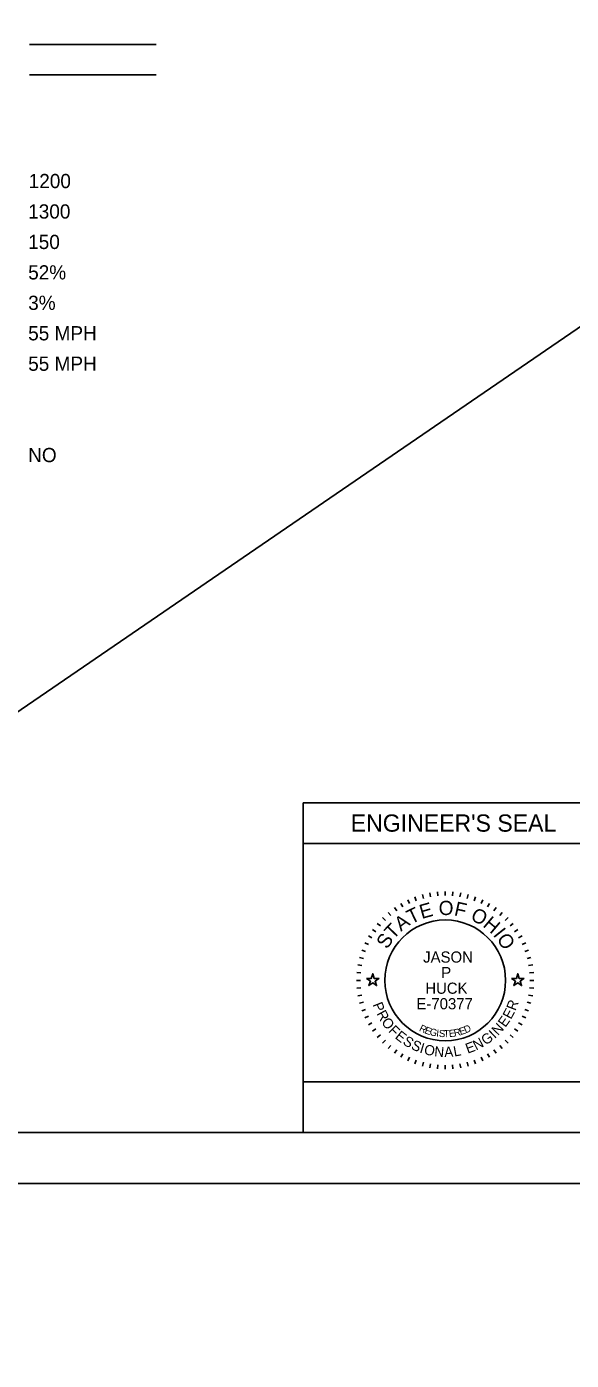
# Model space of a CAD drawing. Extents: x -1.8 to 75.7, y -2 to 25.
# Drawn here: x 7.72 to 13.09, y -1.74 to 11.4 of the extents above; entities that cross this region are included whole.
import ezdxf

# ---------------------------------------------------------------- set-up
doc = ezdxf.new("R2010")
doc.units = 0
for name, color, linetype in [('Default', 7, 'Continuous'), ('SH_Border', 7, 'Continuous'), ('SH_Cut_Line', 7, 'Continuous'), ('SH_Data', 7, 'Continuous'), ('SH_Text', 7, 'Continuous'), ('TX_P_1', 7, 'Continuous')]:
    doc.layers.add(name, color=color, linetype=linetype)

msp = doc.modelspace()

# ---------------------------------------------------------------- linework, layer by layer
at = {"layer": 'Default'}
for points in [[(11.074, 2.02), (11.121, 2.02), (11.135, 2.065), (11.149, 2.02), (11.196, 2.02), (11.158, 1.992), (11.173, 1.948), (11.135, 1.975), (11.097, 1.948), (11.112, 1.992)], [(12.504, 2.02), (12.551, 2.02), (12.565, 2.065), (12.579, 2.02), (12.626, 2.02), (12.588, 1.992), (12.603, 1.948), (12.565, 1.975), (12.527, 1.948), (12.542, 1.992)]]:
    msp.add_lwpolyline(points, close=True, dxfattribs=at)
at = {"layer": 'SH_Border'}
msp.add_lwpolyline([(1.5, 21.5), (33.5, 21.5), (33.5, 0.5), (1.5, 0.5)], close=True, dxfattribs=at)
at = {"layer": 'SH_Cut_Line'}
msp.add_lwpolyline([(0, 0), (34, 0), (34, 22), (0, 22)], close=True, dxfattribs=at)
at = {"layer": 'SH_Data'}
for p, q in [((9, 11.222), (7.75, 11.222)), ((9, 10.922), (7.75, 10.922)), ((13.25, 3.75), (10.45, 3.75)), ((10.45, 3.75), (10.45, 0.5)), ((13.25, 3.35), (10.45, 3.35)), ((11.48, 2.793), (11.497, 2.757)), ((11.551, 2.822), (11.564, 2.785)), ((11.624, 2.845), (11.634, 2.807)), ((11.698, 2.862), (11.705, 2.822)), ((11.774, 2.872), (11.777, 2.832)), ((11.85, 2.875), (11.85, 2.835)), ((11.926, 2.872), (11.923, 2.832)), ((12.002, 2.862), (11.995, 2.822)), ((12.076, 2.845), (12.066, 2.807)), ((12.149, 2.822), (12.136, 2.785)), ((12.22, 2.793), (12.203, 2.757)), ((11.288, 2.67), (11.313, 2.64)), ((11.348, 2.717), (11.371, 2.684)), ((11.413, 2.758), (11.433, 2.723)), ((12.287, 2.758), (12.267, 2.723)), ((12.352, 2.717), (12.329, 2.684)), ((12.412, 2.67), (12.387, 2.64)), ((11.133, 2.502), (11.166, 2.479)), ((11.18, 2.562), (11.21, 2.537)), ((11.231, 2.619), (11.26, 2.59)), ((12.469, 2.619), (12.44, 2.59)), ((12.52, 2.562), (12.49, 2.537)), ((12.567, 2.502), (12.534, 2.479)), ((11.057, 2.37), (11.093, 2.353)), ((11.092, 2.438), (11.127, 2.418)), ((12.608, 2.438), (12.573, 2.418)), ((12.643, 2.37), (12.607, 2.353)), ((11.028, 2.299), (11.065, 2.286)), ((12.672, 2.299), (12.635, 2.286)), ((10.988, 2.152), (11.028, 2.145)), ((11.005, 2.226), (11.043, 2.216)), ((12.695, 2.226), (12.657, 2.216)), ((12.712, 2.152), (12.672, 2.145)), ((10.975, 2), (11.015, 2)), ((10.978, 2.076), (11.018, 2.073)), ((12.722, 2.076), (12.682, 2.073)), ((12.725, 2), (12.685, 2)), ((10.978, 1.924), (11.018, 1.927)), ((10.988, 1.848), (11.028, 1.855)), ((12.712, 1.848), (12.672, 1.855)), ((12.722, 1.924), (12.682, 1.927)), ((11.005, 1.774), (11.043, 1.784)), ((11.028, 1.701), (11.065, 1.714)), ((12.672, 1.701), (12.635, 1.714)), ((12.695, 1.774), (12.657, 1.784)), ((11.057, 1.63), (11.093, 1.647)), ((11.092, 1.563), (11.127, 1.583)), ((12.608, 1.563), (12.573, 1.583)), ((12.643, 1.63), (12.607, 1.647)), ((11.133, 1.498), (11.166, 1.521)), ((11.18, 1.438), (11.21, 1.463)), ((12.52, 1.438), (12.49, 1.463)), ((12.567, 1.498), (12.534, 1.521)), ((11.231, 1.381), (11.26, 1.41)), ((11.288, 1.33), (11.313, 1.36)), ((11.348, 1.283), (11.371, 1.316)), ((12.352, 1.283), (12.329, 1.316)), ((12.412, 1.33), (12.387, 1.36)), ((12.469, 1.381), (12.44, 1.41)), ((11.413, 1.242), (11.433, 1.277)), ((11.48, 1.207), (11.497, 1.243)), ((11.551, 1.178), (11.564, 1.215)), ((11.624, 1.155), (11.634, 1.193)), ((12.076, 1.155), (12.066, 1.193)), ((12.149, 1.178), (12.136, 1.215)), ((12.22, 1.207), (12.203, 1.243)), ((12.287, 1.242), (12.267, 1.277)), ((11.698, 1.138), (11.705, 1.178)), ((11.774, 1.128), (11.777, 1.168)), ((11.85, 1.125), (11.85, 1.165)), ((11.926, 1.128), (11.923, 1.168)), ((12.002, 1.138), (11.995, 1.178)), ((13.25, 0.5), (10.45, 0.5))]:
    msp.add_line(p, q, dxfattribs=at)
msp.add_lwpolyline([(13.25, 0.5), (13.25, 1), (10.45, 1), (10.45, 0.5)], close=True, dxfattribs=at)
msp.add_circle((11.85, 2), 0.595, dxfattribs=at)
at = {"layer": 'TX_P_1'}
msp.add_line((37.367, 24.993), (-1.706, -1.744), dxfattribs=at)

# ---------------------------------------------------------------- texts
at = {"layer": 'SH_Data'}
for s, height, p in [("ENGINEER'S SEAL", 0.17, (10.918, 3.465)), ('JASON', 0.11, (11.632, 2.175)), ('P', 0.11, (11.81, 2.022)), ('HUCK', 0.11, (11.653, 1.868)), ('E-70377', 0.11, (11.566, 1.715))]:
    msp.add_text(s, height=height, dxfattribs=at).set_placement(p)
for s, height, rotation, p in [('E', 0.14, 15.7571, (11.618, 2.604)), ('O', 0.14, 359.7812, (11.785, 2.644)), ('F', 0.14, 347.4362, (11.931, 2.642)), ('A', 0.14, 36.4747, (11.413, 2.478)), ('T', 0.14, 25.7167, (11.512, 2.552)), ('O', 0.14, 332.2586, (12.09, 2.602)), ('H', 0.14, 319.9136, (12.213, 2.536)), ('T', 0.14, 46.4344, (11.338, 2.396)), ('I', 0.14, 308.367, (12.316, 2.448)), ('S', 0.14, 57.1924, (11.278, 2.301)), ('O', 0.14, 303.1491, (12.352, 2.409)), ('P', 0.1, 291.494, (11.132, 1.762)), ('R', 0.1, 298.7311, (11.169, 1.672)), ('E', 0.1, 61.9951, (12.498, 1.61)), ('R', 0.1, 69.2322, (12.542, 1.695)), ('O', 0.1, 306.4666, (11.215, 1.588)), ('N', 0.1, 47.0224, (12.37, 1.451)), ('E', 0.1, 54.758, (12.443, 1.531)), ('F', 0.1, 314.7068, (11.284, 1.498)), ('E', 0.1, 321.4393, (11.348, 1.435)), ('S', 0.1, 328.6764, (11.424, 1.375)), ('R', 0.07, 334.487, (11.587, 1.505)), ('E', 0.07, 341.04, (11.641, 1.48)), ('G', 0.07, 347.4752, (11.691, 1.462)), ('I', 0.07, 353.7858, (11.759, 1.447)), ('S', 0.07, 356.8926, (11.786, 1.443)), ('T', 0.07, 3.0061, (11.836, 1.439)), ('E', 0.07, 6.0117, (11.889, 1.441)), ('R', 0.07, 11.9184, (11.942, 1.447)), ('E', 0.07, 17.6836, (12, 1.46)), ('D', 0.07, 23.3052, (12.051, 1.477)), ('G', 0.1, 35.0469, (12.248, 1.357)), ('I', 0.1, 43.287, (12.337, 1.421)), ('S', 0.1, 335.9134, (11.506, 1.327)), ('I', 0.1, 343.1505, (11.591, 1.29)), ('O', 0.1, 346.8859, (11.634, 1.275)), ('N', 0.1, 355.1261, (11.739, 1.252)), ('A', 0.1, 2.8617, (11.842, 1.244)), ('L', 0.1, 10.0987, (11.939, 1.249)), ('E', 0.1, 20.0742, (12.071, 1.277)), ('N', 0.1, 27.3113, (12.154, 1.308))]:
    msp.add_text(s, height=height, rotation=rotation, dxfattribs=at).set_placement(p)
at = {"layer": 'SH_Text'}
for s, p in [('1200', (7.742, 9.806)), ('1300', (7.737, 9.506)), ('150', (7.737, 9.206)), ('52%', (7.737, 8.906)), ('3%', (7.737, 8.606)), ('55 MPH', (7.737, 8.306)), ('55 MPH', (7.737, 8.006)), ('NO', (7.737, 7.106))]:
    msp.add_text(s, height=0.14, dxfattribs=at).set_placement(p)

doc.saveas('drawing.dxf')
